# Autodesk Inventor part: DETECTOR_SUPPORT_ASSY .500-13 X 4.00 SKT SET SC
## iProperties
Shininess: 64.0
Length Units: 11272
Angle Units: 11279
Time Units: 11290
Mass Units: 11286
Length Display Precision: 3
Angle Display Precision: 2
Compacted: True
Part Number: DETECTOR_SUPPORT_ASSY .500-13 X 4.00 SKT SET SC
Document SubType Name: Modeling
Created: 2004-08
Designer: John Blackburn
Material: MILD_STEEL
Manufacturer: Standard
Standards Organization: Custom
Density: 0.0
Volumn: 0.0
Area: 0.0
PropertySet Name: Model Information
Control State: 0
Master: False
Checked Out: False
Author: John Blackburn
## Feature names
1. Base1
